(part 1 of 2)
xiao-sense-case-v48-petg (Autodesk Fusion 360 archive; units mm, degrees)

design "Xiao Sense Case"
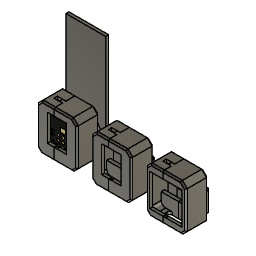
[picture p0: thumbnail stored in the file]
parameter "Clearance" = 0.25
parameter "WallThickness" = 1.6
parameter "HeatSinkWidth" = 10.1
parameter "HeatSinkLength" = 14.3
parameter "PinConnectorOffset" = 1.25 (= "( 2 mm + ( Clearance * 2 ) ) / 2")
parameter "ClearanceBig" = 0.5
parameter "PeepholeDiameterInner" = 10.6
parameter "PeepholeDiameterOuter" = 14.6
parameter "PeepholeHeight" = 2
parameter "AntennaWidth" = 20
parameter "AntennaLength" = 40
parameter "ClearanceSmall" = 0.01
parameter "AntennaTabOffset" = 0.75
parameter "PeepholeSlotWidth" = 2 comment "Actually 2.05"
parameter "CameraRingDiameter" = 7.1
parameter "ThinWallThickness" = 0.8
parameter "d34" = 0.087
base_feature "Base Feature1"
base_feature "Base Feature1"
base_feature "Base Feature1"
base_feature "Base Feature1"
base_feature "Base Feature1"
base_feature "Base Feature1"
base_feature "Base Feature1"
base_feature "Base Feature1"
base_feature "Base Feature1"
base_feature "Base Feature1"
base_feature "Base Feature1"
base_feature "Base Feature1"
base_feature "Base Feature1"
base_feature "Base Feature1"
base_feature "Base Feature1"
base_feature "Base Feature1"
base_feature "Base Feature1"
base_feature "Base Feature1"
base_feature "Base Feature1"
base_feature "Base Feature1"
base_feature "Base Feature1"
base_feature "Base Feature1"
base_feature "Base Feature1"
base_feature "Base Feature1"
base_feature "Base Feature1"
base_feature "Base Feature1"
base_feature "Base Feature1"
base_feature "Base Feature1"
base_feature "Base Feature1"
base_feature "Base Feature1"
base_feature "Base Feature1"
base_feature "Base Feature1"
base_feature "Base Feature1"
base_feature "Base Feature1"
base_feature "Base Feature1"
base_feature "Base Feature1"
sketch "Sketch1" plane through (0, -0.25, 0) normal (0, -1, 0) x axis (1, 0, 0)
  line L1 (0.8736, -12.2817) -> (-13.0964, -12.2817)
  line L2 (2.7786, -10.1227) -> (2.7786, -10.3767)
  line L3 (1.4451, -10.1227) -> (2.7786, -10.1227)
  line L4 (2.7786, -8.5987) -> (1.4451, -8.5987)
  line L5 (2.7786, -7.5827) -> (2.7786, -8.5987)
  line L6 (1.4451, -7.5827) -> (2.7786, -7.5827)
  line L7 (2.7786, -6.0587) -> (1.4451, -6.0587)
  line L8 (2.7786, -5.0427) -> (2.7786, -6.0587)
  line L9 (1.4451, -5.0427) -> (2.7786, -5.0427)
  line L10 (2.7786, -3.5187) -> (1.4451, -3.5187)
  line L11 (2.7786, -2.5027) -> (2.7786, -3.5187)
  line L12 (1.4451, -2.5027) -> (2.7786, -2.5027)
  line L13 (2.7786, -0.9787) -> (1.4451, -0.9787)
  line L14 (2.7786, 0.0373) -> (2.7786, -0.9787)
  line L15 (1.4451, 0.0373) -> (2.7786, 0.0373)
  line L16 (2.7786, 1.5613) -> (1.4451, 1.5613)
  line L17 (2.7786, 2.5773) -> (2.7786, 1.5613)
  line L18 (1.4451, 2.5773) -> (2.7786, 2.5773)
  line L19 (2.7786, 4.1013) -> (1.4451, 4.1013)
  line L20 (2.7786, 5.1173) -> (2.7786, 4.1013)
  line L21 (1.4451, 5.1173) -> (2.7786, 5.1173)
  line L22 (2.7786, 6.6413) -> (1.4451, 6.6413)
  line L23 (2.7786, 6.7683) -> (2.7786, 6.6413)
  line L24 (-13.0964, 8.6733) -> (0.8736, 8.6733)
  line L25 (-15.0014, 6.6413) -> (-15.0014, 6.7683)
  line L26 (-13.6679, 6.6413) -> (-15.0014, 6.6413)
  line L27 (-15.0014, 5.1173) -> (-13.6679, 5.1173)
  line L28 (-15.0014, 4.1013) -> (-15.0014, 5.1173)
  line L29 (-13.6679, 4.1013) -> (-15.0014, 4.1013)
  line L30 (-15.0014, 2.5773) -> (-13.6679, 2.5773)
  line L31 (-15.0014, 1.5613) -> (-15.0014, 2.5773)
  line L32 (-13.6679, 1.5613) -> (-15.0014, 1.5613)
  line L33 (-15.0014, 0.0373) -> (-13.6679, 0.0373)
  line L34 (-15.0014, -0.9787) -> (-15.0014, 0.0373)
  line L35 (-13.6679, -0.9787) -> (-15.0014, -0.9787)
  line L36 (-15.0014, -2.5027) -> (-13.6679, -2.5027)
  line L37 (-15.0014, -3.5187) -> (-15.0014, -2.5027)
  line L38 (-13.6679, -3.5187) -> (-15.0014, -3.5187)
  line L39 (-15.0014, -5.0427) -> (-13.6679, -5.0427)
  line L40 (-15.0014, -6.0587) -> (-15.0014, -5.0427)
  line L41 (-13.6679, -6.0587) -> (-15.0014, -6.0587)
  line L42 (-15.0014, -7.5827) -> (-13.6679, -7.5827)
  line L43 (-15.0014, -8.5987) -> (-15.0014, -7.5827)
  line L44 (-13.6679, -8.5987) -> (-15.0014, -8.5987)
  line L45 (-15.0014, -10.1227) -> (-13.6679, -10.1227)
  line L46 (-15.0014, -10.3767) -> (-15.0014, -10.1227)
  line L47 (-6.3808, 1.5518) -> (-6.3808, -0.9402)
  line L48 (-3.6417, 1.5518) -> (-6.3808, 1.5518)
  line L49 (-3.6417, -0.9402) -> (-3.6417, 1.5518)
  line L50 (-6.3808, -0.9402) -> (-3.6417, -0.9402)
  line L51 (-12.0804, 3.2123) -> (-12.0804, 3.9743)
  line L52 (-12.5884, 3.9743) -> (-12.5884, 3.2123)
  line L53 (-1.5711, -11.6467) -> (-1.5711, -10.7577)
  line L54 (-2.0156, -10.7577) -> (-2.0156, -11.6467)
  line L55 (-10.2071, -7.4557) -> (-10.2071, -6.5667)
  line L56 (-10.6516, -6.5667) -> (-10.6516, -7.4557)
  line L57 (-1.5711, -7.4557) -> (-1.5711, -6.5667)
  line L58 (-2.0156, -6.5667) -> (-2.0156, -7.4557)
  line L59 (-10.2071, -11.6467) -> (-10.2071, -10.7577)
  line L60 (-10.6516, -10.7577) -> (-10.6516, -11.6467)
  line L61 (-11.3184, -2.5027) -> (-9.7944, -2.5027)
  line L62 (-11.4454, -1.8677) -> (-11.4454, -2.3757)
  line L63 (-9.7944, -1.7407) -> (-11.3184, -1.7407)
  line L64 (-9.6674, -2.3757) -> (-9.6674, -1.8677)
  line L65 (-11.3184, -4.4077) -> (-9.7944, -4.4077)
  line L66 (-11.4454, -3.7727) -> (-11.4454, -4.2807)
  line L67 (-9.7944, -3.6457) -> (-11.3184, -3.6457)
  line L68 (-9.6674, -4.2807) -> (-9.6674, -3.7727)
  line L69 (0.3656, 3.2123) -> (0.3656, 3.9743)
  line L70 (-0.1424, 3.9743) -> (-0.1424, 3.2123)
  line L71 (-12.5014, 8.9733) -> (0.2786, 8.9733)
  line L72 (-15.5014, -10.1227) -> (-15.5014, 6.6413)
  line L73 (3.2786, -10.1227) -> (3.2786, 6.6413)
  line L74 (-12.5014, 9.4733) -> (0.2786, 9.4733)
  line L75 (-12.5014, 11.0733) -> (0.2786, 11.0733)
  line L76 (2.7786, 6.1968) -> (2.7786, 6.6413)
  line L77 (4.8786, -10.1227) -> (4.8786, 6.6413)
  line L78 (-15.0014, 6.6413) -> (-15.0014, 6.1968)
  line L79 (-17.1014, -10.1227) -> (-17.1014, 6.6413)
  line L80 (-15.5014, 6.6413) -> (-15.0014, 6.6413)
  line L81 (-15.5014, -10.1227) -> (-15.0014, -10.1227)
  line L82 (3.2786, 6.6413) -> (2.7786, 6.6413)
  line L83 (3.2786, -10.1227) -> (2.7786, -10.1227)
  curve K1 (3.2786, 6.6413) -> (-2.7214, 6.6413)
  curve K2 (0.2786, 9.4733) -> (0.2786, 3.8093)
  line L84 (-6.1114, 9.4733) -> (-6.1114, 8.9733)
  line L85 (-15.5014, -10.3767) -> (-15.5014, -10.1227)
  line L86 (0.8736, -12.7817) -> (-13.0964, -12.7817)
  line L87 (3.2786, -10.1227) -> (3.2786, -10.3767)
  line L88 (-17.1014, -10.3767) -> (-17.1014, -10.1227)
  line L89 (0.8736, -14.3817) -> (-13.0964, -14.3817)
  line L90 (4.8786, -10.1227) -> (4.8786, -10.3767)
  curve K3 (4.8786, 6.6413) -> (-4.3214, 6.6413)
  curve K4 (0.2786, 11.0733) -> (0.2786, 2.2093)
  arc A1 centre (0.8736, -10.3766) radius 1.905 clockwise from (2.7786, -10.3767) to (0.8736, -12.2817)
  arc A2 centre (1.5115, -9.3607) radius 0.7649 clockwise from (1.4451, -10.1227) to (1.4451, -8.5987)
  arc A3 centre (1.5115, -6.8207) radius 0.7649 clockwise from (1.4451, -7.5827) to (1.4451, -6.0587)
  arc A4 centre (1.5115, -4.2807) radius 0.7649 clockwise from (1.4451, -5.0427) to (1.4451, -3.5187)
  arc A5 centre (1.5115, -1.7407) radius 0.7649 clockwise from (1.4451, -2.5027) to (1.4451, -0.9787)
  arc A6 centre (1.5115, 0.7993) radius 0.7649 clockwise from (1.4451, 0.0373) to (1.4451, 1.5613)
  arc A7 centre (1.5115, 3.3393) radius 0.7649 clockwise from (1.4451, 2.5773) to (1.4451, 4.1013)
  arc A8 centre (1.5115, 5.8793) radius 0.7649 clockwise from (1.4451, 5.1173) to (1.4451, 6.6413)
  arc A9 centre (0.8736, 6.7683) radius 1.905 clockwise from (0.8736, 8.6733) to (2.7786, 6.7683)
  arc A10 centre (-13.0964, 6.7683) radius 1.905 clockwise from (-15.0014, 6.7683) to (-13.0964, 8.6733)
  arc A11 centre (-13.7343, 5.8793) radius 0.7649 clockwise from (-13.6679, 6.6413) to (-13.6679, 5.1173)
  arc A12 centre (-13.7343, 3.3393) radius 0.7649 clockwise from (-13.6679, 4.1013) to (-13.6679, 2.5773)
  arc A13 centre (-13.7343, 0.7993) radius 0.7649 clockwise from (-13.6679, 1.5613) to (-13.6679, 0.0373)
  arc A14 centre (-13.7343, -1.7407) radius 0.7649 clockwise from (-13.6679, -0.9787) to (-13.6679, -2.5027)
  arc A15 centre (-13.7343, -4.2807) radius 0.7649 clockwise from (-13.6679, -3.5187) to (-13.6679, -5.0427)
  arc A16 centre (-13.7343, -6.8207) radius 0.7649 clockwise from (-13.6679, -6.0587) to (-13.6679, -7.5827)
  arc A17 centre (-13.7343, -9.3607) radius 0.7649 clockwise from (-13.6679, -8.5987) to (-13.6679, -10.1227)
  arc A18 centre (-13.0964, -10.3766) radius 1.905 clockwise from (-13.0964, -12.2817) to (-15.0014, -10.3767)
  circle C1 centre (-4.8414, -2.7567) radius 0.762
  circle C2 centre (-7.3814, -2.7567) radius 0.762
  circle C3 centre (-4.8414, -10.3767) radius 0.762
  circle C4 centre (-4.8414, -7.8367) radius 0.762
  circle C5 centre (-7.3814, -5.2967) radius 0.762
  arc A19 centre (-12.3344, 3.2123) radius 0.254 clockwise from (-12.0804, 3.2123) to (-12.3344, 2.9583)
  arc A20 centre (-12.3344, 3.2123) radius 0.254 clockwise from (-12.3344, 2.9583) to (-12.5884, 3.2123)
  arc A21 centre (-12.3344, 3.9743) radius 0.254 clockwise from (-12.5884, 3.9743) to (-12.3344, 4.2283)
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  point P187 (-15.0014, 6.6413)
  point P191 (-15.0014, 6.6413)
  point P174 (-15.5014, 6.6413)
  point P192 (-15.5014, 6.6413)
  point P81 (-15.0014, -10.1227)
  point P193 (-15.0014, -10.1227)
  point P175 (-15.5014, -10.1227)
  point P194 (-15.5014, -10.1227)
  point P182 (2.7786, 6.6413)
  point P195 (2.7786, 6.6413)
  point P6 (2.7786, -10.1227)
  point P197 (2.7786, -10.1227)
  point P177 (3.2786, -10.1227)
  point P198 (3.2786, -10.1227)
  point P176 (3.2786, 6.6413)
  point P196 (3.2786, 6.6413)
  point P178 (0.2786, 9.4733)
  point P203 (0.2786, 9.4733)
  point P201 (3.2786, 6.6413)
  point P204 (-6.1114, 8.9733)
  point P205 (-6.1114, 9.4733)
  point P180 (0.2786, 11.0733)
  point P227 (0.2786, 11.0733)
  point P184 (4.8786, 6.6413)
  point P225 (4.8786, 6.6413)
  perpendicular L71 L73
  perpendicular L71 L72
  coincident P187 P191
  perpendicular L78 L80
  coincident P174 P192
  coincident P81 P193
  perpendicular L46 L81
  coincident P175 P194
  coincident P182 P195
  perpendicular L76 L82
  coincident P6 P197
  perpendicular L2 L83
  coincident P177 P198
  coincident P176 P196
  parallel L71 K1
  coincident P178 P203
  coincident P176 P201
  midpoint L71 P204
  midpoint L74 P205
  perpendicular L74 L84
  parallel L71 K3
  coincident P180 P227
  coincident P184 P225
  dimension "d3" = 0.5 (= "ClearanceBig")
  dimension "d4" = 2.1 (= "WallThickness + ClearanceBig")
  dimension "d8" = 1.6 (= "WallThickness")
  dimension "d9" distance P191 P192 = 0.5 (= "ClearanceBig")
  dimension "d12" = 0.5 (= "ClearanceBig")
  dimension "d13" = 2.1 (= "WallThickness + ClearanceBig")
  dimension "d103" distance P195 P196 = 0.5 (= "ClearanceBig")
extrude "Extrude1" new body sketch "Sketch1" blind 2.1 (= "ClearanceBig + WallThickness") Side2Offset 0.5 (= "ClearanceBig")
extrude "Extrude2" add sketch "Sketch1" to an object Side2Offset 0
sketch "Sketch2" plane through (0, -2.35, 0) normal (0, -1, 0) x axis (1, 0, 0)
  line L1 (3.2786, -10.3767) -> (3.2786, 6.6413)
  line L2 (0.2786, 9.4733) -> (-12.5014, 9.4733)
  line L3 (2.7786, 6.6413) -> (1.4451, 6.6413)
  line L4 (1.4451, 5.1173) -> (2.7786, 5.1173)
  line L5 (2.7786, -8.5987) -> (1.4451, -8.5987)
  line L6 (1.4451, -10.1227) -> (2.7786, -10.1227)
  line L7 (-15.0014, -10.1227) -> (-13.6679, -10.1227)
  line L8 (-13.6679, -8.5987) -> (-15.0014, -8.5987)
  line L9 (-13.6679, 6.6413) -> (-15.0014, 6.6413)
  line L10 (-15.0014, 5.1173) -> (-13.6679, 5.1173)
  line L11 (-12.2114, -5.3716) -> (-0.0114, -5.3716)
  line L12 (-12.2114, -5.2716) -> (-12.2114, -5.3716)
  line L13 (-12.2114, 4.7283) -> (-12.2114, -5.2716)
  line L14 (-12.2114, 4.8283) -> (-12.2114, 4.7283)
  line L15 (-0.0114, 4.8283) -> (-12.2114, 4.8283)
  line L16 (-0.0114, 4.7283) -> (-0.0114, 4.8283)
  line L17 (-0.0114, -5.2716) -> (-0.0114, 4.7283)
  line L18 (-0.0114, -5.3716) -> (-0.0114, -5.2716)
  line L19 (-11.4114, -7.6716) -> (-11.4114, 7.1284)
  line L20 (-0.8114, -7.6716) -> (-11.4114, -7.6716)
  line L21 (-0.8114, 7.1284) -> (-0.8114, -7.6716)
  line L22 (-11.4114, 7.1284) -> (-0.8114, 7.1284)
  line L23 (-6.1114, -5.3716) -> (-6.1114, 4.8283)
  line L24 (-0.8114, -0.2716) -> (-11.4114, -0.2716)
  line L25 (2.7786, 6.8913) -> (1.435, 6.8913)
  line L26 (1.435, -10.3727) -> (2.7786, -10.3727)
  line L27 (-15.0014, -10.3727) -> (-13.6679, -10.3727)
  line L28 (-13.6578, 6.8913) -> (-15.0014, 6.8913)
  line L29 (-15.2393, 6.8913) -> (-15.0014, 6.8913)
  line L30 (-12.7194, 6.8913) -> (-13.6578, 6.8913)
  line L31 (-12.7194, -10.3727) -> (-12.7194, 6.8913)
  line L32 (-13.6679, -10.3727) -> (-12.7194, -10.3727)
  line L33 (-15.2514, -10.3727) -> (-15.0014, -10.3727)
  line L34 (-12.7194, -9.3607) -> (-13.7343, -9.3607)
  line L35 (3.2669, 6.8913) -> (2.7786, 6.8913)
  line L36 (3.0286, -10.3727) -> (2.7786, -10.3727)
  line L37 (0.4966, -10.3727) -> (1.435, -10.3727)
  line L38 (0.4966, 6.8913) -> (0.4966, -10.3727)
  line L39 (1.435, 6.8913) -> (0.4966, 6.8913)
  line L40 (0.4966, 5.8793) -> (1.5115, 5.8793)
  line L41 (-13.0964, -12.7817) -> (0.8736, -12.7817)
  line L42 (-15.5014, 6.6413) -> (-15.5014, -10.3767)
  line L43 (-17.1014, -10.3767) -> (-17.1014, 6.6413)
  line L44 (0.8736, -14.3817) -> (-13.0964, -14.3817)
  line L45 (4.8786, -10.1227) -> (4.8786, -10.3767)
  line L46 (4.8786, 6.6413) -> (4.8786, -10.1227)
  line L47 (-12.5014, 11.0733) -> (0.2786, 11.0733)
  closed curve K1 centre (0.2786, 6.6413)
  arc A1 centre (1.5115, 5.8793) radius 0.7649 clockwise from (1.4451, 5.1173) to (1.4451, 6.6413)
  arc A2 centre (1.5115, -9.3607) radius 0.7649 clockwise from (1.4451, -10.1227) to (1.4451, -8.5987)
  arc A3 centre (-13.7343, -9.3607) radius 0.7649 clockwise from (-13.6679, -8.5987) to (-13.6679, -10.1227)
  arc A4 centre (-13.7343, 5.8793) radius 0.7649 clockwise from (-13.6679, 6.6413) to (-13.6679, 5.1173)
  arc A5 centre (1.5115, 5.8793) radius 1.0149 clockwise from (1.4234, 4.8683) to (1.435, 6.8913)
  arc A6 centre (1.5115, -9.3607) radius 1.0149 clockwise from (1.435, -10.3727) to (1.4234, -8.3496)
  arc A7 centre (-13.7343, -9.3607) radius 1.0149 clockwise from (-13.6462, -8.3496) to (-13.6462, -10.3717)
  arc A8 centre (-13.7343, 5.8793) radius 1.0149 clockwise from (-13.6578, 6.8913) to (-13.6462, 4.8683)
  arc A9 centre (0.8736, -10.3766) radius 2.405 clockwise from (3.2786, -10.3767) to (0.8736, -12.7817)
  arc A10 centre (-13.0964, -10.3766) radius 2.405 clockwise from (-13.0964, -12.7817) to (-15.5014, -10.3767)
  closed curve K2 centre (0.2786, 6.6413)
  arc A11 centre (-13.0964, -10.3766) radius 4.005 clockwise from (-13.0964, -14.3817) to (-17.1014, -10.3767)
  arc A12 centre (0.8736, -10.3766) radius 4.005 clockwise from (4.8786, -10.3767) to (0.8736, -14.3817)
  arc A13 centre (-12.6647, 6.6413) radius 2.8367 clockwise from (-15.5014, 6.6413) to (-12.5014, 9.4733)
  closed curve K3 centre (-12.5014, 6.6413)
  point P43 (-11.4114, 7.1284)
  point P47 (-11.4114, 7.1284)
  point P48 (-6.1114, 4.8283)
  point P49 (-6.1114, -5.3716)
  point P50 (-11.4114, -0.2716)
  point P51 (-0.8114, -0.2716)
  point P60 (-13.6679, -10.3727)
  point P72 (-13.6679, -10.3727)
  point P25 (-13.7343, -9.3607)
  point P74 (-13.7343, -9.3607)
  point P75 (-12.7194, -9.3607)
  point P76 (3.2669, 6.8913)
  point P54 (1.435, 6.8913)
  point P80 (1.435, 6.8913)
  point P11 (1.5115, 5.8793)
  point P81 (1.5115, 5.8793)
  point P82 (0.4966, 5.8793)
  point P46 (-0.8114, 7.1284)
  point P45 (-0.8114, -7.6716)
  perpendicular L11 L19
  perpendicular L17 L20
  perpendicular L15 L21
  perpendicular L21 L22
  coincident P43 P47
  midpoint L15 P48
  midpoint L11 P49
  midpoint L19 P50
  midpoint L21 P51
  midpoint L23 L24
  parallel L28 L30
  perpendicular L11 L31
  perpendicular L31 L32
  coincident P60 P72
  coincident P25 P74
  parallel L32 L34
  coincident A7 P75
  coincident L31 P75
  coincident K1 P76
  parallel L26 L37
  perpendicular L37 L38
  perpendicular L38 L39
  coincident P54 P80
  coincident P11 P81
  parallel L25 L40
  coincident A5 P82
  coincident L38 P82
  dimension "d23" distance P46 P47 = 10.6 (= "HeatSinkWidth + ( Clearance * 2 )")
  dimension "d26" distance P45 P46 = 14.8 (= "HeatSinkLength + ( Clearance * 2 )")
  dimension "d27" = 0.25 (= "Clearance")
  dimension "d28" = 0.25 (= "Clearance")
  dimension "d30" = 0.25 (= "Clearance")
  dimension "d31" = 0.25 (= "Clearance")
extrude "Extrude3" add sketch "Sketch2" profile of L1 L2 K1 L11 L12 L13 L14 L15 L16 L17 L18 L19 L20 L21 L22 A5 L25 L26 A6 L27 A8 L28 L29 L30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 no distance stored
sketch "Sketch7" plane through (0, -2.35, 0) normal (0, -1, 0) x axis (1, 0, 0)
  line L1 (-17.1014, -10.3767) -> (-17.1014, 6.6413)
  line L2 (0.8736, -14.3817) -> (-13.0964, -14.3817)
  line L3 (4.8786, -10.1227) -> (4.8786, -10.3767)
  line L4 (4.8786, 6.6413) -> (4.8786, -10.1227)
  line L5 (-13.7314, 7.1293) -> (-13.7314, 5.8793)
  line L6 (-12.4814, 5.8793) -> (-13.7314, 5.8793)
  line L7 (-13.3564, -9.3607) -> (-14.1064, -9.3607)
  line L8 (-13.7314, -10.6107) -> (-13.7314, -9.3607)
  line L9 (1.5086, -10.6107) -> (1.5086, -9.3607)
  line L10 (2.7586, -9.3607) -> (1.5086, -9.3607)
  line L11 (1.1336, 5.8793) -> (1.8836, 5.8793)
  line L12 (1.5086, 7.1293) -> (1.5086, 5.8793)
  line L13 (2.7586, 7.1293) -> (0.2586, 7.1293)
  line L14 (2.7586, -10.6107) -> (2.7586, 7.1293)
  line L15 (0.2586, -10.6107) -> (2.7586, -10.6107)
  line L16 (0.2586, 7.1293) -> (0.2586, -10.6107)
  line L17 (-12.4814, 7.1293) -> (-14.9814, 7.1293)
  line L18 (-12.4814, -10.6107) -> (-12.4814, 7.1293)
  line L19 (-14.9814, -10.6107) -> (-12.4814, -10.6107)
  line L20 (-14.9814, 7.1293) -> (-14.9814, -10.6107)
  line L21 (-0.8114, 7.1284) -> (-11.4114, 7.1284)
  line L22 (-0.8114, -7.6716) -> (-0.8114, 7.1284)
  line L23 (-11.4114, -7.6716) -> (-0.8114, -7.6716)
  line L24 (-11.4114, 7.1284) -> (-11.4114, -7.6716)
  line L25 (-12.5014, 11.0733) -> (0.2786, 11.0733)
  closed curve K1 centre (0.2786, 6.6413)
  arc A1 centre (-13.0964, -10.3766) radius 4.005 clockwise from (-13.0964, -14.3817) to (-17.1014, -10.3767)
  arc A2 centre (0.8736, -10.3766) radius 4.005 clockwise from (4.8786, -10.3767) to (0.8736, -14.3817)
  circle C1 centre (1.5086, -9.3607) radius 0.375
  circle C2 centre (-13.7314, 5.8793) radius 0.375
  closed curve K2 centre (-12.5014, 6.6413)
  point P22 (-13.7314, 5.8793)
  point P23 (-13.7314, 5.8793)
  point P20 (-14.1064, -9.3607)
  point P26 (-14.1064, -9.3607)
  point P21 (-13.3564, -9.3607)
  point P27 (-13.3564, -9.3607)
  point P28 (-13.7314, -9.3607)
  point P17 (1.5086, -9.3607)
  point P30 (1.5086, -9.3607)
  point P16 (1.8836, 5.8793)
  point P34 (1.8836, 5.8793)
  point P15 (1.1336, 5.8793)
  point P35 (1.1336, 5.8793)
  point P36 (1.5086, 5.8793)
  point P37 (1.5086, 7.1293)
  point P33 (2.7586, -9.3607)
  point P32 (1.5086, -9.3607)
  point P31 (1.5086, -10.6107)
  point P29 (-13.7314, -10.6107)
  point P24 (-13.7314, 7.1293)
  point P25 (-12.4814, 5.8793)
  coincident P22 P23
  vertical L5
  perpendicular L5 L6
  coincident P20 P26
  coincident P21 P27
  midpoint L7 P28
  perpendicular L7 L8
  coincident P17 P30
  parallel L4 L9
  perpendicular L9 L10
  coincident P16 P34
  coincident P15 P35
  midpoint L11 P36
  perpendicular L11 L12
  horizontal L13
  vertical L14
  horizontal L15
  vertical L16
  horizontal L17
  vertical L18
  horizontal L19
  vertical L20
  midpoint P37 L13
  coincident P33 L14
  coincident P30 P32
  coincident P31 L15
  midpoint P29 L19
  coincident P24 L17
  coincident P25 L18
  dimension "d76" distance P23 P24 = 1.25 (= "PinConnectorOffset")
  dimension "d77" distance P23 P25 = 1.25 (= "PinConnectorOffset")
  dimension "d79" distance P28 P29 = 1.25 (= "PinConnectorOffset")
  dimension "d80" distance P30 P31 = 1.25 (= "PinConnectorOffset")
  dimension "d82" distance P32 P33 = 1.25 (= "PinConnectorOffset")
  dimension "d83" distance P36 P37 = 1.25 (= "PinConnectorOffset")
extrude "Extrude14" cut sketch "Sketch7" profile of L13 L14 L15 L16 L17 L18 L19 L20 to an object
sketch "Sketch3" plane through (0, -2.35, 0) normal (0, -1, 0) x axis (1, 0, 0)
  line L1 (-17.1014, -10.3767) -> (-17.1014, 6.6413)
  line L2 (0.8736, -14.3817) -> (-13.0964, -14.3817)
  line L3 (4.8786, -10.1227) -> (4.8786, -10.3767)
  line L4 (4.8786, 6.6413) -> (4.8786, -10.1227)
  line L5 (0.2586, 7.1293) -> (-12.4814, 7.1293)
  line L6 (0.2586, 7.1293) -> (0.2586, -10.6107)
  line L7 (2.7586, 7.1293) -> (0.2586, 7.1293)
  line L8 (2.7586, -10.6107) -> (2.7586, 7.1293)
  line L9 (0.2586, -10.6107) -> (2.7586, -10.6107)
  line L10 (-14.9814, 7.1293) -> (-14.9814, -10.6107)
  line L11 (-12.4814, 7.1293) -> (-14.9814, 7.1293)
  line L12 (-12.4814, -10.6107) -> (-12.4814, 7.1293)
  line L13 (-14.9814, -10.6107) -> (-12.4814, -10.6107)
  line L14 (-0.8114, 7.1284) -> (-11.4114, 7.1284)
  line L15 (-0.8114, -7.6716) -> (-0.8114, 7.1284)
  line L16 (-11.4114, -7.6716) -> (-0.8114, -7.6716)
  line L17 (-11.4114, 7.1284) -> (-11.4114, -7.6716)
  line L18 (-12.5014, 11.0733) -> (0.2786, 11.0733)
  line L19 (-11.4114, 7.1293) -> (-11.4114, 7.1284)
  line L20 (-0.8114, 7.1293) -> (-0.8114, 7.1284)
  line L21 (-0.8114, -7.6707) -> (-11.4114, -7.6707)
  closed curve K1 centre (0.2786, 6.6413)
  arc A1 centre (-13.0964, -10.3766) radius 4.005 clockwise from (-13.0964, -14.3817) to (-17.1014, -10.3767)
  arc A2 centre (0.8736, -10.3766) radius 4.005 clockwise from (4.8786, -10.3767) to (0.8736, -14.3817)
  closed curve K2 centre (-12.5014, 6.6413)
  point P23 (-11.4114, 7.1284)
  point P29 (-11.4114, 7.1284)
  point P30 (-11.4114, 7.1293)
  point P24 (-0.8114, 7.1284)
  point P31 (-0.8114, 7.1284)
  point P32 (-0.8114, 7.1293)
  point P14 (0.2586, 7.1293)
  point P16 (0.2586, 7.1293)
  point P13 (-12.4814, 7.1293)
  point P21 (-12.4814, 7.1293)
  point P33 (-11.4114, -7.6707)
  point P34 (-0.8114, -7.6707)
  coincident P23 P29
  coincident L5 P30
  perpendicular L5 L19
  coincident P24 P31
  coincident L5 P32
  perpendicular L5 L20
  horizontal L5
  coincident P14 P16
  coincident P13 P21
  coincident L17 P33
  coincident L15 P34
  perpendicular L15 L21
  dimension "d207" distance L5 L14 = 0.001
  dimension "d208" distance L16 L21 = 0.001 (= "d207")
extrude "Extrude4" add sketch "Sketch3" profile of L15 L16 L17 to an object
extrude "Extrude5" cut sketch "Sketch3" profile of L5 to an object
move "Move2" TranslateX 0 TranslateY 0 TranslateZ 0.67
sketch "Sketch4" plane through (0, 8.28, 0) normal (0, 1, 0) x axis (-1, 0, 0)
  line L1 (12.5014, 9.4733) -> (-0.2786, 9.4733)
  line L2 (15.5014, -10.3767) -> (15.5014, 6.6413)
  line L3 (-0.8736, -12.7817) -> (13.0964, -12.7817)
  line L4 (-3.2786, 6.6413) -> (-3.2786, -10.3767)
  line L5 (-4.8786, -10.1227) -> (-4.8786, 6.6413)
  line L6 (-4.8786, -10.3767) -> (-4.8786, -10.1227)
  line L7 (13.0964, -14.3817) -> (-0.8736, -14.3817)
  line L8 (17.1014, 6.6413) -> (17.1014, -10.3767)
  line L9 (-0.2786, 11.0733) -> (12.5014, 11.0733)
  arc A1 centre (13.0964, -10.3766) radius 2.405 clockwise from (15.5014, -10.3767) to (13.0964, -12.7817)
  arc A2 centre (-0.8736, -10.3766) radius 2.405 clockwise from (-0.8736, -12.7817) to (-3.2786, -10.3767)
  closed curve K1 centre (-0.2786, 6.6413)
  closed curve K2 centre (-0.2786, 6.6413)
  arc A3 centre (-0.8736, -10.3766) radius 4.005 clockwise from (-0.8736, -14.3817) to (-4.8786, -10.3767)
  arc A4 centre (13.0964, -10.3766) radius 4.005 clockwise from (17.1014, -10.3767) to (13.0964, -14.3817)
  closed curve K3 centre (12.5014, 6.6413)
  arc A5 centre (12.6647, 6.6413) radius 2.8367 clockwise from (12.5014, 9.4733) to (15.5014, 6.6413)
extrude "Extrude6" add sketch "Sketch4" profile of L1 L2 A1 L3 A2 L4 K1 K2 L5 L6 A3 L7 A4 L8 along normal blind 1.6 (= "WallThickness")
move "Move1" TranslateX 0 TranslateY 0 TranslateZ -0.5
sketch "Sketch5" plane through (0, 0, -14.3817) normal (0, 0, -1) x axis (1, 0, 0)
  line L1 (0.8736, 2.35) -> (0.8736, -9.88)
  line L2 (-13.0964, 2.35) -> (0.8736, 2.35)
  line L3 (-13.0964, -9.88) -> (-13.0964, 2.35)
  line L4 (0.8736, -9.88) -> (-13.0964, -9.88)
  line L5 (-2.8987, -1) -> (-9.3387, -1)
  line L6 (-10.5887, -2.25) -> (-10.5887, -2.96)
  line L7 (-9.3387, -4.21) -> (-2.8987, -4.21)
  line L8 (-1.6487, -2.96) -> (-1.6487, -2.25)
  line L9 (-0.8367, -6.7) -> (-0.8367, -8.15)
  line L10 (-0.9367, -8.25) -> (-11.9167, -8.25)
  line L11 (-11.9167, -6.6) -> (-0.9367, -6.6)
  line L12 (-12.0167, -8.15) -> (-12.0167, -6.7)
  line L13 (-2.8987, -0.75) -> (-9.3387, -0.75)
  line L14 (-10.8387, -2.25) -> (-10.8387, -2.96)
  line L15 (-9.3387, -4.46) -> (-2.8987, -4.46)
  line L16 (-1.3987, -2.96) -> (-1.3987, -2.25)
  line L17 (-11.9167, -6.35) -> (-0.9367, -6.35)
  line L18 (-12.2667, -8.15) -> (-12.2667, -6.7)
  line L19 (-0.9367, -8.5) -> (-11.9167, -8.5)
  line L20 (-0.5867, -6.7) -> (-0.5867, -8.15)
  arc A1 centre (-2.8987, -2.25) radius 1.25 clockwise from (-2.8987, -1) to (-1.6487, -2.25)
  arc A2 centre (-9.3387, -2.25) radius 1.25 clockwise from (-10.5887, -2.25) to (-9.3387, -1)
  arc A3 centre (-9.3387, -2.96) radius 1.25 clockwise from (-9.3387, -4.21) to (-10.5887, -2.96)
  arc A4 centre (-2.8987, -2.96) radius 1.25 clockwise from (-1.6487, -2.96) to (-2.8987, -4.21)
  arc A5 centre (-0.9367, -8.15) radius 0.1 clockwise from (-0.8367, -8.15) to (-0.9367, -8.25)
  arc A6 centre (-0.9367, -6.7) radius 0.1 clockwise from (-0.9367, -6.6) to (-0.8367, -6.7)
  arc A7 centre (-11.9167, -6.7) radius 0.1 clockwise from (-12.0167, -6.7) to (-11.9167, -6.6)
  arc A8 centre (-11.9167, -8.15) radius 0.1 clockwise from (-11.9167, -8.25) to (-12.0167, -8.15)
  arc A9 centre (-2.8987, -2.25) radius 1.5 clockwise from (-2.8987, -0.75) to (-1.3987, -2.25)
  arc A10 centre (-9.3387, -2.25) radius 1.5 clockwise from (-10.8387, -2.25) to (-9.3387, -0.75)
  arc A11 centre (-9.3387, -2.96) radius 1.5 clockwise from (-9.3387, -4.46) to (-10.8387, -2.96)
  arc A12 centre (-2.8987, -2.96) radius 1.5 clockwise from (-1.3987, -2.96) to (-2.8987, -4.46)
  arc A13 centre (-11.9167, -6.7) radius 0.35 clockwise from (-12.2667, -6.7) to (-11.9167, -6.35)
  arc A14 centre (-11.9167, -8.15) radius 0.35 clockwise from (-11.9167, -8.5) to (-12.2667, -8.15)
  arc A15 centre (-0.9367, -8.15) radius 0.35 clockwise from (-0.5867, -8.15) to (-0.9367, -8.5)
  arc A16 centre (-0.9367, -6.7) radius 0.35 clockwise from (-0.9367, -6.35) to (-0.5867, -6.7)
  dimension "d42" = 0.25 (= "Clearance")
  dimension "d43" = 0.25 (= "Clearance")
extrude "Extrude7" cut sketch "Sketch5" profile of A9 L16 A11 L13 A10 L14 L15 A12 L17 A13 L19 A14 L18 A15 L20 A16 to an object
sketch "Sketch6" plane through (0, 9.88, 0) normal (0, 1, 0) x axis (-1, 0, 0)
  line L1 (-4.8786, -10.1227) -> (-4.8786, 6.6413)
  line L2 (-4.8786, -10.3767) -> (-4.8786, -10.1227)
  line L3 (13.0964, -14.3817) -> (-0.8736, -14.3817)
  line L4 (17.1014, 6.6413) -> (17.1014, -10.3767)
  line L5 (15.5014, 6.6413) -> (15.5014, -10.3767)
  curve K1 (12.5014, 9.4733) -> (15.5014, 6.6413)
  line L6 (-0.2786, 9.4733) -> (12.5014, 9.4733)
  curve K2 (-3.2786, 6.6413) -> (-0.2786, 9.4733)
  line L7 (-3.2786, -10.1227) -> (-3.2786, 6.6413)
  line L8 (-3.2786, -10.3766) -> (-3.2786, -10.1227)
  line L9 (13.0964, -12.7817) -> (-0.8736, -12.7817)
  line L10 (10.08, -4.2817) -> (2.08, -4.2817)
  line L11 (10.08, -12.2817) -> (10.08, -4.2817)
  line L12 (2.08, -12.2817) -> (10.08, -12.2817)
  line L13 (2.08, -4.2817) -> (2.08, -12.2817)
  line L14 (10.58, -12.7817) -> (10.58, -3.7817)
  line L15 (1.58, -12.7817) -> (10.58, -12.7817)
  line L16 (1.58, -3.7817) -> (1.58, -12.7817)
  line L17 (10.58, -3.7817) -> (1.58, -3.7817)
  line L18 (12.18, -14.3817) -> (12.18, -2.1817)
  line L19 (-0.02, -14.3817) -> (12.18, -14.3817)
  line L20 (-0.02, -2.1817) -> (-0.02, -14.3817)
  line L21 (12.18, -2.1817) -> (-0.02, -2.1817)
  line L22 (6.08, -12.2817) -> (6.08, -4.2817)
  line L23 (-0.02, -0.1077) -> (-0.02, -2.1817)
  line L24 (12.18, -0.1077) -> (-0.02, -0.1077)
  line L25 (12.18, -2.1817) -> (12.18, -0.1077)
  line L26 (1.58, -0.1077) -> (1.58, -3.7817)
  line L27 (10.58, -0.1077) -> (10.58, -3.7817)
  line L28 (-0.2786, 11.0733) -> (12.5014, 11.0733)
  line L29 (2.9096, -0.1077) -> (9.8596, -0.1077)
  line L30 (-0.02, 1.4923) -> (-0.02, -0.1077)
  line L31 (12.18, 1.4923) -> (-0.02, 1.4923)
  line L32 (12.18, -0.1077) -> (12.18, 1.4923)
  closed curve K3 centre (-0.2786, 6.6413)
  arc A1 centre (-0.8736, -10.3766) radius 4.005 clockwise from (-0.8736, -14.3817) to (-4.8786, -10.3767)
  arc A2 centre (13.0964, -10.3766) radius 4.005 clockwise from (17.1014, -10.3767) to (13.0964, -14.3817)
  arc A3 centre (13.0964, -10.3766) radius 2.405 clockwise from (15.5014, -10.3767) to (13.0964, -12.7817)
  arc A4 centre (-0.8736, -10.3766) radius 2.405 clockwise from (-0.8736, -12.7817) to (-3.2786, -10.3766)
  circle C1 centre (6.08, -8.2817) radius 3.41
  circle C2 centre (6.08, -8.75) radius 0.75
  closed curve K4 centre (12.5014, 6.6413)
  point P36 (6.08, -4.2817)
  point P38 (6.08, -8.2817)
  point P37 (6.08, -12.2817)
  point P39 (6.08, -8.75)
  point P32 (12.18, -2.1817)
  point P42 (12.18, -2.1817)
  point P43 (1.58, -0.1077)
  point P44 (10.58, -0.1077)
  point P41 (12.18, -0.1077)
  point P51 (12.18, -0.1077)
  point P26 (10.08, -12.2817)
  point P27 (2.08, -12.2817)
  horizontal L10
  vertical L11
  horizontal L12
  vertical L13
  equal L11 L12
  midpoint L10 P36
  midpoint L22 P38
  midpoint L12 P37
  coincident L22 P39
  collinear L3 L19
  perpendicular L21 L23
  perpendicular L20 L24
  perpendicular L21 L25
  coincident P32 P42
  coincident L24 P43
  perpendicular L24 L26
  coincident L24 P44
  perpendicular L24 L27
  concentric A2 A3
  concentric A1 A4
  perpendicular L24 L30
  perpendicular L30 L31
  perpendicular L24 L32
  coincident P41 P51
  collinear L24 L29
  dimension "d50" distance P26 P27 = 8
  dimension "d57" diameter C1 = 6.82 (= "6.32 mm + ( Clearance * 2 )")
  dimension "d106" distance L24 L31 = 1.6 (= "WallThickness")
extrude "Extrude8" cut sketch "Sketch6" profile of L17 L21 L26 L27 to an object
extrude "Extrude9" add sketch "Sketch6" profile of L3 L14 L15 L16 L17 L18 L19 L20 L21 L26 L27 along normal blind 5 (= "4 mm + ( ClearanceBig * 2 )")
extrude "Extrude12" add sketch "Sketch6" profile of L21 L23 L24 L25 L26 L27 L30 L31 L32 along normal blind 0.8 (= "WallThickness / 2")
extrude "Extrude10" sketch "Sketch6" profile of L14 L15 L16 L17 L18 L19 L20 L21 C1 blind 1.6 (= "WallThickness")
extrude "Extrude18" sketch "Sketch6" profile of L21 L23 L24 L25 L26 L27 L30 L31 L32 blind 1.6 (= "WallThickness")
extrude "Extrude11" cut sketch "Sketch6" profile of L17 L21 L26 L27 along normal blind 0.8 (= "WallThickness / 2")
sketch "Sketch10" plane through (0, 16.48, 0) normal (0, 1, 0) x axis (-1, 0, 0)
  line L1 (-0.02, -2.1817) -> (12.18, -2.1817)
  line L2 (-0.02, -14.3817) -> (-0.02, -2.1817)
  line L3 (12.18, -14.3817) -> (-0.02, -14.3817)
  line L4 (12.18, -2.1817) -> (12.18, -14.3817)
  line L5 (-4.4855, -8.2817) -> (0.7972, 0.8683)
  line L6 (0.7972, -17.4317) -> (-4.4855, -8.2817)
  line L7 (11.3628, -17.4317) -> (0.7972, -17.4317)
  line L8 (16.6455, -8.2817) -> (11.3628, -17.4317)
  line L9 (11.3628, 0.8683) -> (16.6455, -8.2817)
  line L10 (0.7972, 0.8683) -> (11.3628, 0.8683)
  line L11 (-0.02, 1.4923) -> (12.18, 1.4923)
  line L12 (-5.206, -8.2817) -> (0.437, 1.4923)
  line L13 (0.437, -18.0556) -> (-5.206, -8.2817)
  line L14 (11.723, -18.0556) -> (0.437, -18.0556)
  line L15 (17.366, -8.2817) -> (11.723, -18.0556)
  line L16 (11.723, 1.4923) -> (17.366, -8.2817)
  line L17 (0.437, 1.4923) -> (11.723, 1.4923)
  line L18 (16.6455, -8.2817) -> (-4.4855, -8.2817)
  line L19 (6.08, -17.4317) -> (6.08, 0.8683)
  line L20 (1.1064, -7.4067) -> (-1.4191, -7.4067)
  line L21 (1.1064, -9.1567) -> (1.1064, -7.4067)
  line L22 (-1.4191, -9.1567) -> (1.1064, -9.1567)
  line L23 (11.0536, -7.4067) -> (13.5791, -7.4067)
  line L24 (11.0536, -9.1567) -> (11.0536, -7.4067)
  line L25 (13.5791, -9.1567) -> (11.0536, -9.1567)
  circle C1 centre (6.08, -8.2817) radius 3.41
  circle C2 centre (6.08, -8.2817) radius 5.3
  circle C3 centre (6.08, -8.2817) radius 7.3
  circle C4 centre (6.08, -8.2817) radius 5.05
  circle C5 centre (6.08, -8.2817) radius 7.55
  circle C6 centre (6.08, -8.2817) radius 9.15
  circle C7 centre (6.08, -8.2817) radius 3.8
  point P4 (6.08, -8.2817)
  point P18 (6.08, -8.2817)
  point P3 (6.08, -8.2817)
  point P27 (6.08, -8.2817)
  point P28 (6.08, 0.8683)
  point P29 (6.08, -17.4317)
  point P30 (-1.4191, -7.4067)
  point P33 (-1.4191, -9.1567)
  point P32 (1.1064, -9.1567)
  point P34 (13.5791, -7.4067)
  point P31 (1.1064, -7.4067)
  point P35 (11.0536, -7.4067)
  point P36 (11.0536, -9.1567)
  point P37 (13.5791, -9.1567)
  point P38 (6.08, -8.2817)
  concentric C1 C2
  concentric C1 C3
  coincident P4 P18
  parallel L1 L10
  coincident P3 P27
  parallel L11 L17
  midpoint L10 P28
  midpoint L7 P29
  coincident C5 P30
  horizontal L20
  perpendicular L20 L21
  perpendicular L21 L22
  coincident C5 P33
  coincident C4 P32
  symmetric L19 P30 P34
  symmetric L19 P31 P35
  symmetric L19 P32 P36
  symmetric L19 P33 P37
  coincident P27 P38
  dimension "d113" diameter C2 = 10.6 (= "PeepholeDiameterInner")
  dimension "d114" diameter C3 = 14.6 (= "PeepholeDiameterOuter")
  dimension "d116" = 0.25 (= "Clearance")
  dimension "d117" = 1.85 (= "WallThickness + Clearance")
  dimension "d360" distance L18 L20 = 0.875 (= "( PeepholeSlotWidth - Clearance ) / 2")
  dimension "d361" distance L18 L22 = 0.875 (= "d360")
  dimension "d375" diameter C7 = 7.6
move "Move1" TranslateX -0.468 TranslateY 2.43 TranslateZ 0
extrude "Extrude22" cut sketch "Sketch10" profile of C1 C4 C5 C6 L1 L2 L3 L4 L20 L21 L22 L23 L24 L25 C7 to an object offset 3.8 (= "3 mm + ThinWallThickness")
extrude "Extrude23" sketch "Sketch10" profile of C5 C6 L1 L2 L3 L4 L5 L6 L7 L8 L9 L10 L11 L12 L13 L14 L15 L16 L17 blind 2.25 (= "PeepholeHeight + Clearance")
extrude "Extrude24" add of existing geometry to an object
extrude "Extrude25" add of existing geometry to an object
extrude "Extrude26" add of existing geometry to an object
extrude "Extrude27" add of existing geometry to an object
extrude "Extrude28" sketch "Sketch10" profile of C5 L3 to an object
extrude "Extrude83" sketch "Sketch10" profile of C4 C5 L2 L4 L20 L21 L22 L23 L24 L25 to an object
extrude "Extrude84" add of existing geometry to an object
extrude "Extrude85" add of existing geometry to an object
extrude "Extrude87" sketch "Sketch10" profile of C4 C5 L1 L2 L3 L4 L20 L21 L22 L23 L24 L25 C7 no distance stored
work_plane "WorkPlane1"
sketch "Sketch11" plane through (-6.08, 0, 0) normal (1, 0, 0) x axis (0, 1, 0)
  line L1 (15.23, 0.8683) -> (15.23, -17.4317)
  line L2 (12.98, -0.7317) -> (12.98, -15.8317)
  line L3 (12.98, -14.3817) -> (9.88, -14.3817)
  line L4 (12.93, -17.4317) -> (9.88, -14.3817)
  line L5 (12.93, -17.4317) -> (15.23, -17.4317)
  line L6 (9.88, -17.4317) -> (12.93, -17.4317)
  line L7 (9.88, -14.3817) -> (9.88, -17.4317)
  line L8 (9.88, -18.0556) -> (15.93, -18.0556)
  line L9 (13.554, -18.0556) -> (12.93, -17.4317)
  line L10 (9.88, -17.4317) -> (9.88, -18.0556)
  point P2 (9.88, -14.3817)
  point P7 (9.88, -14.3817)
  point P8 (12.98, -14.3817)
  point P9 (9.88, -14.3817)
  point P3 (15.23, -17.4317)
  point P11 (15.23, -17.4317)
  point P10 (12.93, -17.4317)
  point P12 (12.93, -17.4317)
  point P14 (9.88, -14.3817)
  point P17 (13.554, -18.0556)
  point P16 (9.88, -18.0556)
  point P18 (9.88, -18.0556)
  coincident P2 P7
  coincident L2 P8
  perpendicular L2 L3
  coincident P2 P9
  coincident P3 P11
  perpendicular L1 L5
  coincident P10 P12
  perpendicular L1 L6
  perpendicular L6 L7
  coincident P9 P14
  coincident L8 P17
  parallel L4 L9
  coincident P16 P18
  dimension "d143" angle L3 L4 = 45
extrude "Extrude29" cut sketch "Sketch11" profile of L4 L6 L7 L8 L9 L10 to an object Side2Offset 0
extrude "Extrude34" cut of existing geometry to an object
sketch "Sketch12" plane through (0, 8.28, 0) normal (0, -1, 0) x axis (1, 0, 0)
  line L1 (-1.58, -3.7817) -> (-1.58, -0.1077)
  line L2 (-10.58, -3.7817) -> (-1.58, -3.7817)
  line L3 (-10.58, -0.1077) -> (-10.58, -3.7817)
  line L4 (-1.58, -0.1077) -> (-10.58, -0.1077)
  line L5 (-12.2417, -12.7817) -> (-13.0964, -12.7817)
  line L6 (3.2786, 6.6413) -> (3.2786, -10.3767)
  line L7 (-12.5014, 9.4733) -> (0.2786, 9.4733)
  line L8 (-15.5014, -10.3767) -> (-15.5014, 6.6413)
  line L9 (-12.18, 1.4923) -> (-12.18, 0.7008)
  line L10 (-11.723, 1.4923) -> (-12.18, 1.4923)
  line L11 (0.02, 0.7008) -> (0.02, 1.4923)
  line L12 (-11.0025, 1.4923) -> (-11.3628, 0.8683)
  line L13 (-1.1575, 1.4923) -> (-0.7972, 0.8683)
  line L14 (-2.58, 0.8683) -> (-9.58, 0.8683)
  line L15 (-9.58, -3.7817) -> (-9.58, 0.8683)
  line L16 (-2.58, -3.7817) -> (-2.58, 0.8683)
  line L17 (-10.58, -3.7817) -> (-10.58, -0.1077)
  line L18 (-1.58, -3.7817) -> (-10.58, -3.7817)
  line L19 (-1.58, -0.1077) -> (-1.58, -3.7817)
  line L20 (-10.58, -0.1077) -> (-1.58, -0.1077)
  line L21 (-12.18, 0.7008) -> (-11.723, 1.4923)
  line L22 (-0.437, 1.4923) -> (0.02, 0.7008)
  line L23 (0.02, 1.4923) -> (-0.437, 1.4923)
  line L24 (-0.6117, -12.7817) -> (-12.2417, -12.7817)
  line L25 (0.8736, -12.7817) -> (-0.6117, -12.7817)
  arc A1 centre (0.8736, -10.3766) radius 2.405 clockwise from (3.2786, -10.3767) to (0.8736, -12.7817)
  closed curve K1 centre (0.2786, 6.6413)
  arc A2 centre (-12.6647, 6.6413) radius 2.8367 clockwise from (-15.5014, 6.6413) to (-12.5014, 9.4733)
  arc A3 centre (-13.0964, -10.3766) radius 2.405 clockwise from (-13.0964, -12.7817) to (-15.5014, -10.3767)
  point P24 (-11.0025, 1.4923)
  point P26 (-1.1575, 1.4923)
  point P29 (-9.58, -3.7817)
  point P30 (-2.58, -3.7817)
  point P27 (-9.58, 0.8683)
  point P28 (-2.58, 0.8683)
  coincident L10 P24
  coincident L10 P26
  parallel L4 L14
  coincident L2 P29
  perpendicular L2 L15
  coincident L2 P30
  perpendicular L2 L16
  dimension "d150" distance P27 P28 = 7 (= "6 mm + ( ClearanceBig * 2 )")
extrude "Extrude31" add sketch "Sketch12" profile of L1 L2 L3 L4 L15 L16 L17 L18 L19 L20 to an object
extrude "Extrude32" sketch "Sketch12" profile of L9 L10 L11 L21 L22 L23 to an object
sketch "Sketch13" plane through (0, -2.35, 0) normal (0, -1, 0) x axis (1, 0, 0)
  line L1 (-0.8114, -7.6707) -> (-0.8114, 7.1293)
  line L2 (-11.4114, 7.1293) -> (-11.4114, -7.6707)
  line L3 (-0.8114, 7.1293) -> (-11.4114, 7.1293)
  line L4 (0.2586, 7.1293) -> (0.2586, -10.6107)
  line L5 (2.7586, 7.1293) -> (0.2586, 7.1293)
  line L6 (2.7586, -10.6107) -> (2.7586, 7.1293)
  line L7 (0.2586, -10.6107) -> (2.7586, -10.6107)
  line L8 (-14.9814, 7.1293) -> (-14.9814, -10.6107)
  line L9 (-12.4814, 7.1293) -> (-14.9814, 7.1293)
  line L10 (-12.4814, -10.6107) -> (-12.4814, 7.1293)
  line L11 (-14.9814, -10.6107) -> (-12.4814, -10.6107)
  line L12 (-12.5014, 11.0733) -> (0.2786, 11.0733)
  line L13 (-17.1014, -10.3767) -> (-17.1014, 6.6413)
  line L14 (0.8736, -14.3817) -> (-13.0964, -14.3817)
  line L15 (4.8786, -10.1227) -> (4.8786, -10.3767)
  line L16 (4.8786, 6.6413) -> (4.8786, -10.1227)
  line L17 (2.2343, 11.0733) -> (0.2786, 11.0733)
  line L18 (4.8786, 8.429) -> (2.2343, 11.0733)
  line L19 (4.8786, 8.429) -> (4.8786, 6.6413)
  line L20 (4.8786, -12.0356) -> (4.8786, -10.1227)
  line L21 (2.5325, -14.3817) -> (4.8786, -12.0356)
  line L22 (0.8736, -14.3817) -> (2.5325, -14.3817)
  line L23 (-17.1014, -12.0356) -> (-17.1014, -10.3767)
  line L24 (-14.7553, -14.3817) -> (-17.1014, -12.0356)
  line L25 (-13.0964, -14.3817) -> (-14.7553, -14.3817)
  line L26 (-17.1014, 8.429) -> (-17.1014, 6.6413)
  line L27 (-14.4571, 11.0733) -> (-17.1014, 8.429)
  line L28 (-12.5014, 11.0733) -> (-14.4571, 11.0733)
  line L29 (-11.4114, -7.6707) -> (-0.8114, -7.6707)
  closed curve K1 centre (0.2786, 6.6413)
  closed curve K2 centre (-12.5014, 6.6413)
  arc A1 centre (-13.0964, -10.3766) radius 4.005 clockwise from (-13.0964, -14.3817) to (-17.1014, -10.3767)
  arc A2 centre (0.8736, -10.3766) radius 4.005 clockwise from (4.8786, -10.3767) to (0.8736, -14.3817)
  point P15 (0.2786, 11.0733)
  point P27 (0.2786, 11.0733)
  point P14 (4.8786, 6.6413)
  point P30 (4.8786, 6.6413)
  point P29 (4.8786, 8.429)
  point P31 (4.8786, 8.429)
  point P26 (4.8786, -10.1227)
  point P32 (4.8786, -10.1227)
  point P23 (0.8736, -14.3817)
  point P35 (0.8736, -14.3817)
  point P20 (-17.1014, -10.3767)
  point P36 (-17.1014, -10.3767)
  point P21 (-13.0964, -14.3817)
  point P39 (-13.0964, -14.3817)
  point P18 (-17.1014, 6.6413)
  point P40 (-17.1014, 6.6413)
  point P17 (-12.5014, 11.0733)
  point P43 (-12.5014, 11.0733)
  coincident P15 P27
  tangent K1 L17
  parallel L12 L17
  coincident P14 P30
  tangent K1 L19
  perpendicular L12 L19
  coincident P29 P31
  tangent K1 L18
  coincident P26 P32
  parallel L15 L20
  perpendicular L15 L22
  coincident P23 P35
  tangent A2 L21
  coincident P20 P36
  parallel L13 L23
  perpendicular L13 L25
  coincident P21 P39
  tangent A1 L24
  coincident P18 P40
  tangent K2 L26
  parallel L13 L26
  perpendicular L26 L28
  coincident P17 P43
  tangent K2 L27
  dimension "d161" angle L17 L18 = 135
  dimension "d162" angle L20 L21 = 135
  dimension "d163" angle L24 L25 = 135
  dimension "d164" angle L26 L27 = 135
extrude "Extrude33" add sketch "Sketch13" profile of K1 K2 A1 A2 L17 L18 L19 L20 L21 L22 L23 L24 L25 L26 L27 L28 to an object
sketch "Sketch14" plane through (4.8786, 0, 0) normal (1, 0, 0) x axis (0, 1, 0)
  line L1 (-2.35, -10.1227) -> (-2.35, 8.429)
  line L2 (9.88, -10.1227) -> (-2.35, -10.1227)
  line L3 (9.88, -8.8487) -> (9.88, -10.1227)
  line L4 (15.93, -8.8487) -> (9.88, -8.8487)
  line L5 (15.93, -7.7146) -> (15.93, -8.8487)
  line L6 (9.88, -7.7146) -> (15.93, -7.7146)
  line L7 (9.88, 8.429) -> (9.88, -7.7146)
  line L8 (-2.35, 8.429) -> (9.88, 8.429)
  line L9 (9.88, -12.0356) -> (-2.35, -12.0356)
  line L10 (-2.35, -12.0356) -> (-2.35, -10.1227)
  line L11 (9.88, -12.0356) -> (9.88, -10.1227)
  point P3 (-2.35, -10.1227)
  point P12 (-2.35, -10.1227)
  point P10 (-2.35, -12.0356)
  point P13 (-2.35, -12.0356)
  point P4 (9.88, -10.1227)
  point P14 (9.88, -10.1227)
  point P11 (9.88, -12.0356)
  point P15 (9.88, -12.0356)
  coincident P3 P12
  coincident P10 P13
  coincident P4 P14
  coincident P11 P15
extrude "Extrude35" add sketch "Sketch14" along normal blind 1
extrude "Extrude36" cut of existing geometry blind -1
chamfer "Chamfer4" distance 0.8 (= "WallThickness / 2")
work_plane "WorkPlane4" RotateAngle -45
sketch "Sketch22" plane through (-0.1868, 0, 0.1868) normal (-0.7071, 0, 0.7071) x axis (0, 1, 0)
  line L1 (9.88, 19.9587) -> (9.88, 20.6029)
  line L2 (9.88, 20.6029) -> (-2.35, 20.6029)
  line L3 (9.08, 20.6029) -> (9.88, 19.9587)
  point P3 (9.88, 19.9587)
  point P5 (9.88, 19.9587)
  point P6 (9.08, 20.6029)
  point P2 (9.88, 20.6029)
  coincident P3 P5
  coincident L2 P6
  dimension "d223" distance P2 P6 = 0.8 (= "WallThickness / 2")
extrude "Extrude50" cut sketch "Sketch22" to an object Side2Offset 0
work_plane "WorkPlane5" RotateAngle 45
sketch "Sketch23" plane through (-5.9246, 0, -5.9246) normal (0.7071, 0, 0.7071) x axis (0, 1, 0)
  line L1 (9.88, -11.9601) -> (9.88, -11.3603)
  line L2 (9.88, -11.9601) -> (-2.35, -11.9601)
  line L3 (9.08, -11.9601) -> (9.88, -11.3603)
  point P2 (9.88, -11.3603)
  point P5 (9.88, -11.3603)
  point P6 (9.08, -11.9601)
  point P3 (9.88, -11.9601)
  coincident P2 P5
  coincident L2 P6
  dimension "d229" distance P3 P6 = 0.8 (= "WallThickness / 2")
extrude "Extrude51" cut sketch "Sketch23" to an object Side2Offset 0
chamfer "Chamfer1" distance 0.8 (= "WallThickness / 2")
split "Split1"
extrude "Extrude15" cut of existing geometry to an object
sketch "Sketch8" plane through (-6.08, 0, 0) normal (-1, 0, 0) x axis (0, -1, 0)
  line L1 (-12.88, -12.7817) -> (-9.88, -12.7817)
  line L2 (-8.5, -12.7817) -> (-12.88, -12.7817)
  line L3 (-8.5, -14.3817) -> (-9.88, -14.3817)
  line L4 (-8.28, -3.7817) -> (-8.28, -12.7817)
  line L5 (-9.88, -3.7817) -> (-8.28, -3.7817)
  line L6 (-9.88, -12.7817) -> (-9.88, -3.7817)
  line L7 (-8.5, -12.7817) -> (-8.5, -14.3817)
  line L8 (-13.68, -15.8317) -> (-13.68, -12.0817)
  line L9 (-15.93, -15.8317) -> (-13.68, -15.8317)
  line L10 (-15.93, -18.0556) -> (-15.93, -15.8317)
  line L11 (-9.88, -14.3817) -> (-13.554, -18.0556)
  line L12 (-13.554, -18.0556) -> (-15.93, -18.0556)
  line L13 (-8.28, -12.7817) -> (-8.5, -12.7817)
  line L14 (-12.88, -12.0817) -> (-12.88, -12.7817)
  line L15 (-13.68, -12.0817) -> (-12.88, -12.0817)
extrude "Extrude16" add sketch "Sketch8" profile of L2 L4 L5 L6 L13 to an object offset 0.01 (= "ClearanceSmall")
sketch "Sketch9" plane through (0, 0, 11.0733) normal (0, 0, 1) x axis (-1, 0, 0)
  line L1 (6.75, -8.83) -> (6.75, 1.3)
  line L2 (12.5014, -8.83) -> (6.75, -8.83)
  line L3 (12.5014, 1.3) -> (12.5014, -8.83)
  line L4 (6.75, 1.3) -> (12.5014, 1.3)
  line L5 (-0.8736, -1) -> (13.0964, -1)
  line L6 (12.5014, -3.93) -> (-0.2786, -3.93)
  line L7 (12.3881, -3.93) -> (12.3881, -1)
  line L8 (9.2881, -1) -> (9.2881, -3.93)
  line L9 (6.08, -9.08) -> (6.08, 1.55)
  line L10 (6.08, 1.55) -> (14.4571, 1.55)
  line L11 (14.4571, -9.08) -> (6.08, -9.08)
  line L12 (14.4571, 1.55) -> (14.4571, -9.08)
  line L13 (9.2881, -2.465) -> (12.3881, -2.465)
  line L14 (12.3881, -4.1225) -> (12.3881, -3.93)
  line L15 (9.2881, -4.1225) -> (12.3881, -4.1225)
  line L16 (9.2881, -3.93) -> (9.2881, -4.1225)
  line L17 (12.3881, -2.2725) -> (12.3881, -2.465)
  line L18 (9.2881, -2.2725) -> (12.3881, -2.2725)
  point P12 (12.3881, -1)
  point P13 (12.3881, -3.93)
  point P14 (9.2881, -3.93)
  point P15 (9.2881, -1)
  point P20 (12.3881, -2.465)
  point P21 (9.2881, -2.465)
  point P24 (9.2881, -3.93)
  point P25 (12.3881, -2.2725)
  point P26 (9.2881, -2.2725)
  point P10 (12.1381, -1.35)
  point P11 (9.5381, -1.35)
  coincident L5 P12
  coincident L6 P13
  perpendicular L6 L7
  coincident L6 P14
  coincident L5 P15
  perpendicular L5 L8
  midpoint L7 P20
  midpoint L8 P21
  perpendicular L6 L14
  perpendicular L7 L15
  perpendicular L15 L16
  coincident P14 P24
  coincident L7 P25
  perpendicular L13 L17
  coincident L8 P26
  perpendicular L8 L18
  equal L14 L17
  dimension "d95" distance P10 L7 = 0.25 (= "Clearance")
  dimension "d96" distance P11 L8 = 0.25 (= "Clearance")
  dimension "d240" distance L15 L18 = 1.85 (= "WallThickness + Clearance")
extrude "Extrude17" cut sketch "Sketch9" profile of L6 L7 L8 L13 L14 L15 L16 L18 to an object
sketch "Sketch15" plane through (0, 0, 11.0733) normal (0, 0, 1) x axis (-1, 0, 0)
  line L1 (6.08, 1.55) -> (6.08, -9.08)
  line L2 (-2.2343, 1.55) -> (6.08, 1.55)
  line L3 (-2.2343, -9.08) -> (-2.2343, 1.55)
  line L4 (6.08, -9.08) -> (-2.2343, -9.08)
  line L5 (9.2881, -2.2725) -> (9.2881, -4.1225)
  line L6 (6.08, -4.1225) -> (9.2881, -4.1225)
  line L7 (6.08, -2.2725) -> (9.2881, -2.2725)
  line L8 (6.08, -4.1125) -> (9.2881, -4.1125)
  line L9 (6.08, -2.2825) -> (9.2881, -2.2825)
  point P6 (9.2881, -4.1225)
  point P8 (9.2881, -4.1225)
  point P9 (6.08, -4.1225)
  point P7 (9.2881, -2.2725)
  point P10 (9.2881, -2.2725)
  point P11 (6.08, -2.2725)
  coincident P6 P8
  coincident L1 P9
  perpendicular L1 L6
  coincident P7 P10
  coincident L1 P11
  perpendicular L1 L7
  dimension "d234" = 0.01 (= "ClearanceSmall")
extrude "Extrude37" cut sketch "Sketch15" profile of L1 L5 L6 L7 to an object
extrude "Extrude38" add sketch "Sketch15" profile of L1 L5 L8 L9 to an object
sketch "Sketch16" plane through (0, 0, -12.7817) normal (0, 0, 1) x axis (-1, 0, 0)
  line L1 (6.08, -6.35) -> (6.08, -4.46)
  line L2 (11.9167, -6.35) -> (6.08, -6.35)
  line L3 (12.2667, -8.15) -> (12.2667, -6.7)
  line L4 (13.0964, -8.28) -> (12.2417, -8.28)
  line L5 (13.0964, 0.75) -> (13.0964, -8.28)
  line L6 (6.08, 0.75) -> (13.0964, 0.75)
  line L7 (6.08, -0.75) -> (6.08, 0.75)
  line L8 (9.3387, -0.75) -> (6.08, -0.75)
  line L9 (10.8387, -2.96) -> (10.8387, -2.25)
  line L10 (6.08, -4.46) -> (9.3387, -4.46)
  line L11 (15.5014, 0.75) -> (15.5014, -8.28)
  line L12 (-3.2786, 0.75) -> (-3.2786, -8.28)
  line L13 (15.5014, -6.35) -> (6.08, -6.35)
  line L14 (15.5014, -4.46) -> (6.08, -4.46)
  line L15 (-3.2786, -6.35) -> (6.08, -6.35)
  line L16 (-3.2786, -4.46) -> (6.08, -4.46)
  arc A1 centre (11.9167, -6.7) radius 0.35 clockwise from (11.9167, -6.35) to (12.2667, -6.7)
  arc A2 centre (11.9167, -8.15) radius 0.35 clockwise from (12.2667, -8.15) to (12.2417, -8.28)
  arc A3 centre (9.3387, -2.25) radius 1.5 clockwise from (9.3387, -0.75) to (10.8387, -2.25)
  arc A4 centre (9.3387, -2.96) radius 1.5 clockwise from (10.8387, -2.96) to (9.3387, -4.46)
  point P3 (6.08, -6.35)
  point P24 (6.08, -6.35)
  point P25 (15.5014, -6.35)
  point P2 (6.08, -4.46)
  point P26 (6.08, -4.46)
  point P27 (15.5014, -4.46)
  point P28 (-3.2786, -6.35)
  point P29 (-3.2786, -4.46)
  coincident P3 P24
  coincident L11 P25
  perpendicular L11 L13
  coincident P2 P26
  coincident L11 P27
  perpendicular L11 L14
  coincident L12 P28
  perpendicular L12 L15
  coincident L12 P29
  perpendicular L12 L16
extrude "Extrude39" add sketch "Sketch16" profile of L1 L2 L5 L10 L11 L13 L14 to an object offset 0.5 (= "ClearanceBig")
extrude "Extrude40" add sketch "Sketch16" profile of L1 L12 L15 L16 to an object offset 0.5 (= "ClearanceBig")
